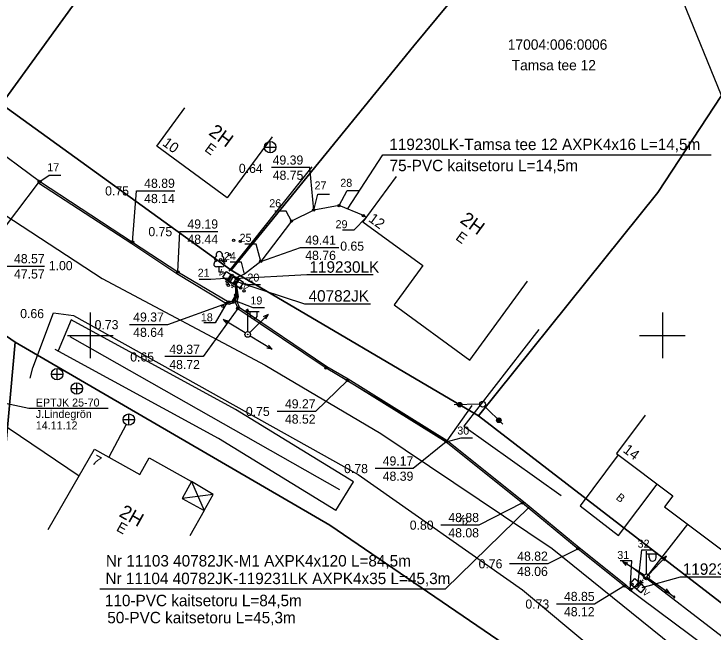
# Model space of a CAD drawing. Extents: x 643977 to 644381, y 6457457 to 6457867.
# Drawn here: x 644193.3 to 644254.5, y 6457574.1 to 6457628.1 of the extents above; entities that cross this region are included whole.
import ezdxf

# ---------------------------------------------------------------- set-up
doc = ezdxf.new("R2010")
doc.units = 0
for name, color, linetype in [('004 MPP EE @ 1 (1)', 7, 'Continuous'), ('005 MPO EE @ 1 (1)', 7, 'Continuous'), ('005 MPO EE @ 1 (2)', 7, 'Continuous'), ('007 PIIR EE', 7, 'Continuous'), ('007 PIIR1 EE', 7, 'Continuous'), ('010 TXT EE', 7, 'Continuous'), ('015 RAIE EE', 7, 'Continuous'), ('020 RAAM', 7, 'Continuous'), ('MOOTMPUNKT', 7, 'Continuous'), ('TEE', 7, 'Continuous'), ('TORU_NR', 7, 'Continuous'), ('UUS', 7, 'Continuous'), ('Veeprojekti jooned$0$0_Hoiatustekst', 7, 'Continuous'), ('VORK', 7, 'Continuous'), ('VORMISTUS', 7, 'Continuous')]:
    doc.layers.add(name, color=color, linetype=linetype)

# ---------------------------------------------------------------- blocks, each defined once
blk = doc.blocks.new('PUPOST')
at = {"layer": '005 MPO EE @ 1 (1)'}
blk.add_circle((0, 0), 0.5, dxfattribs=at)
blk = doc.blocks.new('vapost')
for p, q in [((0, 0.5), (0, 4.5)), ((0, 4), (2, 4)), ((0.45, 3.36), (0.45, 4)), ((1.68, 3.36), (1.68, 4))]:
    blk.add_line(p, q)
blk.add_arc((1.07, 3.36), 0.613, 180, 0)
blk = doc.blocks.new('MPSUUN')
at = {"layer": '007 PIIR EE'}
for p, q in [((0, 0), (0, 0)), ((0.5, 0), (5, 0)), ((5, 0), (4.1, 0.3)), ((5, 0), (4.1, -0.3))]:
    blk.add_line(p, q, dxfattribs=at)
blk = doc.blocks.new('ANKURP')
for start, end in [(0, 180), (180, 0)]:
    blk.add_arc((0, 0), 0.125, start, end)

msp = doc.modelspace()

# ---------------------------------------------------------------- linework, layer by layer
at = {"layer": '004 MPP EE @ 1 (1)'}
msp.add_line((644239.199, 6457600.529), (644232.652, 6457592.057), dxfattribs=at)
at = {"layer": '005 MPO EE @ 1 (1)'}
for p, q in [((644212.29, 6457605.331), (644211.961, 6457604.833)), ((644212.516, 6457605.181), (644212.187, 6457604.683)), ((644212.779, 6457605.045), (644212.45, 6457604.547)), ((644213.005, 6457604.895), (644212.676, 6457604.397)), ((644213.758, 6457600.332), (644213.758, 6457602.332)), ((644213.758, 6457602.082), (644214.758, 6457602.082)), ((644213.984, 6457601.761), (644213.984, 6457602.082)), ((644214.597, 6457601.761), (644214.597, 6457602.082)), ((644248.608, 6457578.893), (644251.036, 6457577.131)), ((644247.929, 6457578.434), (644247.542, 6457577.979)), ((644248.135, 6457578.258), (644247.749, 6457577.803))]:
    msp.add_line(p, q, dxfattribs=at)
for points in [[(644211.905, 6457605.585), (644212.901, 6457604.927), (644212.572, 6457604.429), (644211.576, 6457605.087)], [(644212.394, 6457605.299), (644213.39, 6457604.641), (644213.061, 6457604.143), (644212.065, 6457604.801)], [(644247.577, 6457578.733), (644248.487, 6457577.959), (644248.101, 6457577.504), (644247.19, 6457578.278)]]:
    msp.add_lwpolyline(points, close=True, dxfattribs=at)
for points in [[(644212.597, 6457604.969), (644218.94, 6457605.335), (644224.711, 6457605.335)], [(644213.14, 6457604.587), (644218.721, 6457602.77), (644224.504, 6457602.77)], [(644248.226, 6457577.956), (644251.586, 6457578.9), (644257.011, 6457578.9)]]:
    msp.add_lwpolyline(points, dxfattribs=at)
for centre, radius in [((644213.758, 6457600.082), 0.25), ((644213.758, 6457600.082), 0.0234), ((644234.282, 6457593.981), 0.25)]:
    msp.add_circle(centre, radius, dxfattribs=at)
msp.add_arc((644214.291, 6457601.761), 0.306, 180, 0, dxfattribs=at)
at = {"layer": '005 MPO EE @ 1 (2)'}
for points in [[(644165.209, 6457630.911), (644174.337, 6457623.878), (644186.272, 6457614.624), (644201.035, 6457604.979), (644215.289, 6457597.386), (644225.394, 6457591.42), (644240.377, 6457581.381), (644253.475, 6457570.785), (644267.864, 6457559.308)], [(644194.761, 6457596.256), (644194.987, 6457597.157), (644196.798, 6457601.965), (644198.523, 6457601.742), (644223.424, 6457587.828)], [(644246.147, 6457589.551), (644242.802, 6457585.101), (644246.149, 6457582.509), (644249.531, 6457587.008)], [(644223.424, 6457587.828), (644237.787, 6457577.75), (644250.576, 6457567.066), (644264.806, 6457556.67)]]:
    msp.add_lwpolyline(points, dxfattribs=at)
at = {"layer": '007 PIIR EE'}
for p, q in [((644213.936, 6457600.257), (644215.545, 6457601.83)), ((644215.545, 6457601.83), (644215.118, 6457601.622)), ((644215.545, 6457601.83), (644215.326, 6457601.408)), ((644211.62, 6457601.378), (644211.928, 6457601.016)), ((644211.62, 6457601.378), (644212.083, 6457601.271)), ((644213.544, 6457600.211), (644211.62, 6457601.378)), ((644213.971, 6457599.952), (644215.895, 6457598.785)), ((644215.895, 6457598.785), (644215.432, 6457598.893)), ((644215.895, 6457598.785), (644215.587, 6457599.148))]:
    msp.add_line(p, q, dxfattribs=at)
at = {"layer": '007 PIIR1 EE'}
msp.add_line((644252.198, 6457583.497), (644248.608, 6457578.893), dxfattribs=at)
for points in [[(644170.747, 6457632.71), (644170.727, 6457632.25), (644170.665, 6457631.798), (644170.489, 6457631.288), (644176.355, 6457627.696), (644180.988, 6457624.699), (644187.779, 6457619.88), (644190.918, 6457616.922), (644195.569, 6457613.471), (644203.702, 6457608.165), (644207.658, 6457605.551), (644212.132, 6457602.911), (644212.432, 6457603.018), (644212.719, 6457603.524), (644212.727, 6457604.721)], [(644170.747, 6457632.71), (644170.727, 6457632.25), (644170.665, 6457631.798), (644170.489, 6457631.288), (644176.355, 6457627.696), (644180.988, 6457624.699), (644187.779, 6457619.88), (644190.918, 6457616.922), (644195.569, 6457613.471), (644203.702, 6457608.165), (644207.658, 6457605.551), (644212.132, 6457602.911), (644212.432, 6457603.018), (644212.719, 6457603.524), (644212.727, 6457604.721)], [(644222.474, 6457611.048), (644225.557, 6457615.795), (644254.262, 6457615.795)], [(644219.531, 6457610.954), (644219.186, 6457614.673), (644215.852, 6457614.673)], [(644187.622, 6457602.896), (644188.506, 6457603.833), (644191.675, 6457608.319), (644195.483, 6457613.348), (644203.62, 6457608.04), (644207.578, 6457605.424), (644211.895, 6457602.8), (644212.158, 6457602.721), (644212.49, 6457602.886), (644212.75, 6457603.471), (644212.727, 6457604.721)], [(644187.622, 6457602.896), (644188.506, 6457603.833), (644191.675, 6457608.319), (644195.483, 6457613.348), (644203.62, 6457608.04), (644207.578, 6457605.424), (644211.895, 6457602.8), (644212.158, 6457602.721), (644212.49, 6457602.886), (644212.75, 6457603.471), (644212.727, 6457604.721)], [(644203.702, 6457608.165), (644204.047, 6457612.634), (644207.381, 6457612.634)], [(644224.103, 6457610.306), (644223.868, 6457610.476), (644221.749, 6457611.344), (644219.531, 6457610.954), (644217.585, 6457609.995), (644214.896, 6457606.473), (644213.477, 6457605.348), (644212.855, 6457605.089), (644212.238, 6457605.007)], [(644224.103, 6457610.306), (644223.868, 6457610.476), (644221.749, 6457611.344), (644219.531, 6457610.954), (644217.585, 6457609.995), (644214.896, 6457606.473), (644213.477, 6457605.348), (644212.855, 6457605.089), (644212.238, 6457605.007)], [(644207.658, 6457605.551), (644207.826, 6457609.073), (644211.159, 6457609.073)], [(644191.675, 6457608.319), (644192.671, 6457606.04), (644196.005, 6457606.04)], [(644214.896, 6457606.473), (644218.378, 6457607.69), (644221.711, 6457607.69)], [(644212.315, 6457604.549), (644211.786, 6457604.901)], [(644212.238, 6457605.007), (644212.051, 6457604.725)], [(644212.121, 6457604.498), (644211.814, 6457604.702)], [(644211.926, 6457604.447), (644211.843, 6457604.503)], [(644212.807, 6457604.263), (644212.276, 6457604.612)], [(644212.613, 6457604.211), (644212.305, 6457604.413)], [(644212.419, 6457604.159), (644212.335, 6457604.214)], [(644212.727, 6457604.721), (644212.541, 6457604.437)], [(644212.727, 6457604.721), (644212.787, 6457603.384), (644212.635, 6457602.989), (644212.886, 6457602.359), (644220.606, 6457597.153), (644222.47, 6457596.063), (644231.114, 6457590.695), (644237.777, 6457585.353), (644242.629, 6457581.344), (644246.678, 6457578.098), (644259.713, 6457568.388), (644262.891, 6457566.699), (644271.921, 6457560.313), (644279.137, 6457556.219), (644280.27, 6457555.988)], [(644212.727, 6457604.721), (644212.787, 6457603.384), (644212.635, 6457602.989), (644212.886, 6457602.359), (644220.606, 6457597.153), (644222.47, 6457596.063), (644231.114, 6457590.695), (644237.777, 6457585.353), (644242.629, 6457581.344), (644246.678, 6457578.098), (644259.713, 6457568.388), (644262.891, 6457566.699), (644271.921, 6457560.313), (644279.137, 6457556.219), (644280.27, 6457555.988)], [(644212.727, 6457604.721), (644212.938, 6457603.359), (644212.796, 6457602.99), (644213.008, 6457602.457), (644220.686, 6457597.28), (644222.547, 6457596.191), (644231.201, 6457590.818), (644237.872, 6457585.469), (644242.724, 6457581.46), (644246.77, 6457578.217), (644247.219, 6457577.8), (644247.839, 6457578.119)], [(644212.727, 6457604.721), (644212.938, 6457603.359), (644212.796, 6457602.99), (644213.008, 6457602.457), (644220.686, 6457597.28), (644222.547, 6457596.191), (644231.201, 6457590.818), (644237.872, 6457585.469), (644242.724, 6457581.46), (644246.77, 6457578.217), (644247.219, 6457577.8), (644247.839, 6457578.119)], [(644211.895, 6457602.8), (644206.756, 6457600.938), (644203.422, 6457600.938)], [(644212.886, 6457602.359), (644209.858, 6457598.146), (644206.524, 6457598.146)], [(644222.47, 6457596.063), (644219.678, 6457593.35), (644216.345, 6457593.35)], [(644188.326, 6457594.977), (644188.697, 6457594.667), (644188.76, 6457594.652), (644199.031, 6457587.724)], [(644188.326, 6457594.977), (644194.624, 6457593.629), (644201.578, 6457593.629)], [(644231.114, 6457590.695), (644228.224, 6457588.357), (644224.89, 6457588.357)], [(644237.777, 6457585.353), (644233.959, 6457583.41), (644230.626, 6457583.41)], [(644200.846, 6457577.854), (644231.056, 6457577.828), (644238.356, 6457584.994)], [(644242.629, 6457581.344), (644239.975, 6457580.032), (644236.642, 6457580.032)], [(644247.836, 6457578.583), (644248.302, 6457578.151)], [(644248.036, 6457578.602), (644248.306, 6457578.353)], [(644248.236, 6457578.622), (644248.31, 6457578.554)], [(644246.678, 6457578.098), (644244.064, 6457576.51), (644240.731, 6457576.51)], [(644247.839, 6457578.119), (644248.069, 6457578.367)]]:
    msp.add_lwpolyline(points, dxfattribs=at)
at = {"layer": '010 TXT EE'}
for p, q in [((644215.23, 6457616.455), (644216.23, 6457616.455)), ((644215.73, 6457615.955), (644215.73, 6457616.955)), ((644197.101, 6457596.11), (644197.101, 6457597.11)), ((644196.601, 6457596.61), (644197.601, 6457596.61)), ((644198.819, 6457594.854), (644198.819, 6457595.854)), ((644198.319, 6457595.354), (644199.319, 6457595.354)), ((644202.862, 6457592.638), (644203.862, 6457592.638)), ((644203.362, 6457592.138), (644203.362, 6457593.138))]:
    msp.add_line(p, q, dxfattribs=at)
for centre in [(644215.73, 6457616.455), (644197.101, 6457596.61), (644198.819, 6457595.354), (644203.362, 6457592.638)]:
    msp.add_circle(centre, 0.5, dxfattribs=at)
at = {"layer": '015 RAIE EE'}
msp.add_line((644203.128, 6457592.196), (644201.623, 6457589.351), dxfattribs=at)
at = {"layer": '020 RAAM'}
for p, q in [((644208.853, 6457587.213), (644209.942, 6457584.683)), ((644210.739, 6457586.103), (644208.034, 6457585.754))]:
    msp.add_line(p, q, dxfattribs=at)
at = {"layer": 'Defpoints'}
for points in [[(644215.895, 6457617.35), (644211.952, 6457612.041), (644205.817, 6457616.548), (644208.274, 6457619.892)], [(644226.72, 6457613.899), (644223.834, 6457609.936), (644229.067, 6457606.125), (644226.549, 6457602.668), (644233.18, 6457597.84), (644238.195, 6457604.728)], [(644248.488, 6457593.021), (644245.977, 6457589.68), (644250.898, 6457585.981), (644250.174, 6457585.019), (644255.762, 6457580.818), (644256.522, 6457581.827), (644261.477, 6457578.102), (644263.952, 6457581.395)], [(644196.319, 6457583.018), (644200.373, 6457590.053), (644204.333, 6457587.83), (644205.152, 6457589.29), (644208.853, 6457587.213), (644208.034, 6457585.754), (644209.942, 6457584.683), (644208.711, 6457582.489)], [(644209.942, 6457584.683), (644210.739, 6457586.103), (644208.853, 6457587.213)]]:
    msp.add_lwpolyline(points, dxfattribs=at)
at = {"layer": 'MOOTMPUNKT'}
for centre in [(644195.533, 6457613.47), (644195.599, 6457613.449), (644219.531, 6457610.954), (644221.749, 6457611.344), (644223.868, 6457610.476), (644217.585, 6457609.995), (644203.702, 6457608.165), (644212.525, 6457608.313), (644213.115, 6457608.235), (644211.391, 6457606.623), (644212.149, 6457607.052), (644211.805, 6457606.521), (644214.896, 6457606.473), (644207.658, 6457605.551), (644212.403, 6457605.256), (644212.892, 6457604.97), (644212.072, 6457604.386), (644213.133, 6457604.152), (644212.719, 6457603.524), (644213.441, 6457603.885), (644212.132, 6457602.911), (644212.49, 6457602.886), (644212.635, 6457602.989), (644212.787, 6457603.384), (644211.587, 6457602.549), (644211.895, 6457602.8), (644212.886, 6457602.359), (644213.71, 6457602.168), (644220.606, 6457597.153), (644222.47, 6457596.063), (644231.114, 6457590.695), (644237.777, 6457585.353), (644242.629, 6457581.344), (644246.678, 6457578.098), (644247.333, 6457578.24), (644248.032, 6457578.346), (644247.216, 6457577.773), (644247.219, 6457577.8)]:
    msp.add_circle(centre, 0.1, dxfattribs=at)
at = {"layer": 'TEE'}
msp.add_lwpolyline([(644119.21, 6457655.5), (644137.18, 6457639.57), (644176.94, 6457610.8), (644193.44, 6457599.42), (644220.94, 6457583.42), (644258.83, 6457557.54), (644299.64, 6457526.51), (644330.13, 6457505.12), (644351.66, 6457500.83), (644373.13, 6457501.25), (644368.81, 6457508.24), (644366.6, 6457513.63), (644352.78, 6457513.35), (644335.16, 6457516.88), (644304.29, 6457538.7), (644233.94, 6457592.97), (644213.34, 6457605.08), (644212.32, 6457605.7), (644192.23, 6457620.22), (644172.44, 6457634.51), (644128.57, 6457664.58), (644105.62, 6457695.4)], dxfattribs=at)
for points in [[(644226.91, 6457668.24), (644207.22, 6457681.69), (644202.24, 6457674.99), (644172.44, 6457634.51), (644192.23, 6457620.22), (644221.58, 6457660.75)], [(644239.59, 6457656.82), (644226.91, 6457668.24), (644221.58, 6457660.75), (644192.23, 6457620.22), (644212.32, 6457605.7), (644228.29, 6457625.32), (644245.1, 6457645.66)], [(644249.59, 6457612.49), (644255.15, 6457620.97), (644245.1, 6457645.66), (644228.29, 6457625.32), (644212.32, 6457605.7), (644213.34, 6457605.08), (644233.94, 6457592.97)], [(644233.94, 6457592.97), (644304.29, 6457538.7), (644328.42, 6457571.95), (644255.15, 6457620.97), (644249.59, 6457612.49)], [(644176.94, 6457610.8), (644154.49, 6457578.04), (644187.08, 6457554.88), (644191.21, 6457575.04), (644193.44, 6457599.42)], [(644187.08, 6457554.88), (644204.95, 6457528.94), (644258.83, 6457557.54), (644220.94, 6457583.42), (644193.44, 6457599.42), (644191.21, 6457575.04)]]:
    msp.add_lwpolyline(points, close=True, dxfattribs=at)
at = {"layer": 'TORU_NR'}
for p, q in [((644212.146, 6457605.617), (644219.403, 6457614.751)), ((644198.344, 6457601.348), (644197.194, 6457598.64)), ((644198.206, 6457599.892), (644221.783, 6457586.521)), ((644232.652, 6457592.057), (644241.137, 6457586.014)), ((644258.034, 6457571.483), (644247.502, 6457579.582))]:
    msp.add_line(p, q, dxfattribs=at)
for points in [[(644221.473, 6457584.697), (644223.001, 6457587.195), (644212.679, 6457593.512), (644198.344, 6457601.348)], [(644221.473, 6457584.697), (644211.211, 6457590.977), (644196.94, 6457598.779)], [(644221.825, 6457596.432), (644231.185, 6457590.781), (644233.385, 6457593.88)]]:
    msp.add_lwpolyline(points, dxfattribs=at)
at = {"layer": 'UUS'}
for points in [[(644195.599, 6457613.449), (644196.422, 6457614.02), (644197.422, 6457614.02)], [(644219.531, 6457610.954), (644219.894, 6457612.353), (644220.894, 6457612.353)], [(644221.749, 6457611.344), (644222.459, 6457612.659), (644223.459, 6457612.659)], [(644217.585, 6457609.995), (644217.132, 6457610.874), (644216.132, 6457610.874)], [(644224.103, 6457610.306), (644223.045, 6457609.197), (644222.045, 6457609.197)], [(644214.896, 6457606.473), (644214.509, 6457607.971), (644213.509, 6457607.971)], [(644213.477, 6457605.348), (644213.214, 6457606.405), (644212.214, 6457606.405)], [(644212.238, 6457605.007), (644210.523, 6457604.876), (644209.523, 6457604.876)], [(644212.727, 6457604.721), (644213.867, 6457604.452), (644214.867, 6457604.452)], [(644212.624, 6457603.051), (644214.212, 6457602.449), (644215.212, 6457602.449)], [(644211.963, 6457602.893), (644210.917, 6457601.096), (644209.917, 6457601.096)], [(644231.114, 6457590.695), (644232.417, 6457591.056), (644233.417, 6457591.056)], [(644247.839, 6457578.119), (644248.195, 6457581.246), (644249.195, 6457581.246)], [(644247.184, 6457577.769), (644247.317, 6457580.289), (644246.317, 6457580.289)]]:
    msp.add_lwpolyline(points, dxfattribs=at)
at = {"layer": 'Veeprojekti jooned$0$0_Hoiatustekst'}
for p, q in [((644234.032, 6457593.976), (644231.792, 6457593.931)), ((644234.461, 6457593.805), (644236.057, 6457592.233))]:
    msp.add_line(p, q, dxfattribs=at)
for centre, radius in [((644232.288, 6457593.941), 0.199), ((644232.288, 6457593.941), 0.19), ((644232.288, 6457593.941), 0.18), ((644232.288, 6457593.941), 0.171), ((644232.288, 6457593.941), 0.162), ((644232.288, 6457593.941), 0.152), ((644232.288, 6457593.941), 0.143), ((644232.288, 6457593.941), 0.133), ((644232.288, 6457593.941), 0.124), ((644232.288, 6457593.941), 0.114), ((644232.288, 6457593.941), 0.105), ((644232.288, 6457593.941), 0.0953), ((644232.288, 6457593.941), 0.0858), ((644232.288, 6457593.941), 0.0763), ((644232.288, 6457593.941), 0.0669), ((644232.288, 6457593.941), 0.0574), ((644232.288, 6457593.941), 0.0479), ((644232.288, 6457593.941), 0.0385), ((644232.288, 6457593.941), 0.029), ((644232.288, 6457593.941), 0.0195), ((644232.288, 6457593.941), 0.0101), ((644232.288, 6457593.941), 0.00061), ((644235.704, 6457592.581), 0.199), ((644235.704, 6457592.581), 0.19), ((644235.704, 6457592.581), 0.18), ((644235.704, 6457592.581), 0.171), ((644235.704, 6457592.581), 0.162), ((644235.704, 6457592.581), 0.152), ((644235.704, 6457592.581), 0.143), ((644235.704, 6457592.581), 0.133), ((644235.704, 6457592.581), 0.124), ((644235.704, 6457592.581), 0.114), ((644235.704, 6457592.581), 0.105), ((644235.704, 6457592.581), 0.0953), ((644235.704, 6457592.581), 0.0858), ((644235.704, 6457592.581), 0.0763), ((644235.704, 6457592.581), 0.0669), ((644235.704, 6457592.581), 0.0574), ((644235.704, 6457592.581), 0.0479), ((644235.704, 6457592.581), 0.0385), ((644235.704, 6457592.581), 0.029), ((644235.704, 6457592.581), 0.0195), ((644235.704, 6457592.581), 0.0101), ((644235.704, 6457592.581), 0.00061)]:
    msp.add_circle(centre, radius, dxfattribs=at)
at = {"layer": 'VORK'}
for p, q in [((644200, 6457602), (644200, 6457598)), ((644250, 6457602), (644250, 6457598)), ((644198, 6457600), (644202, 6457600)), ((644248, 6457600), (644252, 6457600))]:
    msp.add_line(p, q, dxfattribs=at)
at = {"layer": 'VORMISTUS'}
for p, q in [((644211.511, 6457605.999), (644211.031, 6457605.999)), ((644211.271, 6457605.524), (644211.271, 6457605.999)), ((644211.651, 6457605.524), (644211.271, 6457605.524))]:
    msp.add_line(p, q, dxfattribs=at)
for centre, radius, start, end in [((644211.271, 6457607.044), 0.277, 332.5799, 207.4201), ((644211.101, 6457606.697), 0.233, 109.02174, 253.14154), ((644211.441, 6457606.697), 0.233, 286.85082, 70.98591), ((644211.033, 6457606.236), 0.238, 90.0016, 269.3953), ((644211.508, 6457606.236), 0.238, 270.6047, 89.9984)]:
    msp.add_arc(centre, radius, start, end, dxfattribs=at)

# ---------------------------------------------------------------- block references
at = {"layer": '005 MPO EE @ 1 (1)', "xscale": 0.5, "yscale": 0.5}
for name, p in [('vapost', (644248.608, 6457578.893)), ('PUPOST', (644248.608, 6457578.893)), ('ANKURP', (644251.036, 6457577.131))]:
    msp.add_blockref(name, p, dxfattribs=at)
at = {"layer": '007 PIIR EE'}
for xscale, yscale, rotation in [(0.5, 0.49999999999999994, 147.3314534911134), (0.5, 0.5, 46.27880571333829), (0.5000000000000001, 0.4999999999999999, -35.36986530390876)]:
    msp.add_blockref('MPSUUN', (644248.608, 6457578.893), dxfattribs=dict(at, xscale=xscale, yscale=yscale, rotation=rotation))

# ---------------------------------------------------------------- texts
at = {"layer": '005 MPO EE @ 1 (1)'}
for s, p in [('119230LK', (644219.155, 6457605.48)), ('40782JK', (644219.078, 6457602.952)), ('119231LK', (644251.781, 6457579.069))]:
    msp.add_text(s, height=1, dxfattribs=at).set_placement(p)
for p in [(644211.1, 6457605.398), (644213.202, 6457604.175), (644248.205, 6457577.443)]:
    msp.add_text('V', height=0.56, rotation=320.19443, dxfattribs=at).set_placement(p)
at = {"layer": '005 MPO EE @ 1 (2)'}
for s, rotation, p in [('B', 320.00064, (644245.879, 6457585.731)), ('Kr', 324.94206, (644232.135, 6457583.792))]:
    msp.add_text(s, height=0.7, rotation=rotation, dxfattribs=at).set_placement(p)
at = {"layer": '007 PIIR1 EE'}
for s, height, p in [('119230LK-Tamsa tee 12 AXPK4x16 L=14,5m', 1, (644226.135, 6457616.205)), ('49.39', 0.8, (644215.937, 6457614.93)), ('75-PVC kaitsetoru L=14,5m', 1, (644226.159, 6457614.355)), ('0.64', 0.8, (644212.986, 6457614.204)), ('48.75', 0.8, (644215.947, 6457613.606)), ('48.89', 0.8, (644204.714, 6457612.9)), ('0.75', 0.8, (644201.301, 6457612.234)), ('48.14', 0.8, (644204.714, 6457611.567)), ('49.19', 0.8, (644208.492, 6457609.339)), ('0.75', 0.8, (644205.079, 6457608.673)), ('48.44', 0.8, (644208.492, 6457608.006)), ('49.41', 0.8, (644218.788, 6457607.933)), ('0.65', 0.8, (644221.846, 6457607.405)), ('48.76', 0.8, (644218.788, 6457606.6)), ('48.57', 0.8, (644193.338, 6457606.307)), ('1.00', 0.8, (644196.377, 6457605.7)), ('47.57', 0.8, (644193.338, 6457604.974)), ('0.66', 0.8, (644193.878, 6457601.509)), ('49.37', 0.8, (644203.754, 6457601.202)), ('0.73', 0.8, (644200.38, 6457600.536)), ('48.64', 0.8, (644203.754, 6457599.869)), ('49.37', 0.8, (644206.905, 6457598.384)), ('0.65', 0.8, (644203.492, 6457597.717)), ('48.72', 0.8, (644206.905, 6457597.051)), ('EPTJK 25-70', 0.7, (644195.242, 6457593.781)), ('49.27', 0.8, (644217.012, 6457593.617)), ('J.Lindegrön', 0.7, (644195.242, 6457592.781)), ('0.75', 0.8, (644213.599, 6457592.95)), ('48.52', 0.8, (644217.012, 6457592.284)), ('14.11.12', 0.7, (644195.242, 6457591.781)), ('49.17', 0.8, (644225.557, 6457588.624)), ('0.78', 0.8, (644222.184, 6457587.957)), ('48.39', 0.8, (644225.557, 6457587.29)), ('48.88', 0.8, (644231.293, 6457583.676)), ('0.80', 0.8, (644227.92, 6457583.01)), ('48.08', 0.8, (644231.293, 6457582.343)), ('48.82', 0.8, (644237.309, 6457580.299)), ('Nr 11103 40782JK-M1 AXPK4x120 L=84,5m', 1, (644201.37, 6457579.795)), ('0.76', 0.8, (644233.936, 6457579.632)), ('48.06', 0.8, (644237.309, 6457578.965)), ('Nr 11104 40782JK-119231LK AXPK4x35 L=45,3m', 1, (644201.331, 6457578.256)), ('110-PVC kaitsetoru L=84,5m', 1, (644201.281, 6457576.323)), ('48.85', 0.8, (644241.397, 6457576.777)), ('0.73', 0.8, (644238.024, 6457576.11)), ('48.12', 0.8, (644241.397, 6457575.443)), ('50-PVC kaitsetoru L=45,3m', 1, (644201.489, 6457574.829))]:
    msp.add_text(s, height=height, dxfattribs=at).set_placement(p)
at = {"layer": 'Defpoints'}
for s, height, rotation, p in [('2H', 1.2, 323.70001, (644210.276, 6457617.595)), ('10', 0.9, 323.70001, (644206.237, 6457616.669)), ('E', 0.9, 323.70001, (644209.925, 6457616.176)), ('12', 0.9, 323.94117, (644224.243, 6457610.031)), ('2H', 1.2, 323.94117, (644232.24, 6457609.924)), ('E', 0.9, 323.94117, (644231.859, 6457608.43)), ('14', 0.9, 323.0655, (644246.49, 6457589.846)), ('7', 0.9, 330.6988, (644200.062, 6457588.823)), ('2H', 1.2, 330.6988, (644202.44, 6457584.223)), ('E', 0.9, 330.6988, (644202.206, 6457582.964))]:
    msp.add_text(s, height=height, rotation=rotation, dxfattribs=at).set_placement(p)
at = {"layer": 'TEE'}
for s, p in [('17004:006:0006', (644236.487, 6457624.977)), ('Tamsa tee 12', (644236.831, 6457623.177))]:
    msp.add_text(s, height=0.9, dxfattribs=at).set_placement(p)
at = {"layer": 'UUS'}
for s, p in [(' 17', (644195.987, 6457614.352)), (' 27', (644219.341, 6457612.764)), (' 28', (644221.59, 6457612.991)), (' 26', (644215.382, 6457611.205)), (' 29', (644221.177, 6457609.371)), (' 25', (644212.788, 6457608.184)), (' 24', (644211.42, 6457606.586)), (' 21', (644209.128, 6457605.129)), (' 20', (644213.472, 6457604.705)), (' 19', (644213.738, 6457602.702)), (' 18', (644209.404, 6457601.232)), (' 30', (644231.815, 6457591.329)), (' 32', (644247.573, 6457581.44)), (' 31', (644245.794, 6457580.453))]:
    msp.add_text(s, height=0.7, dxfattribs=at).set_placement(p)

doc.saveas('drawing.dxf')
